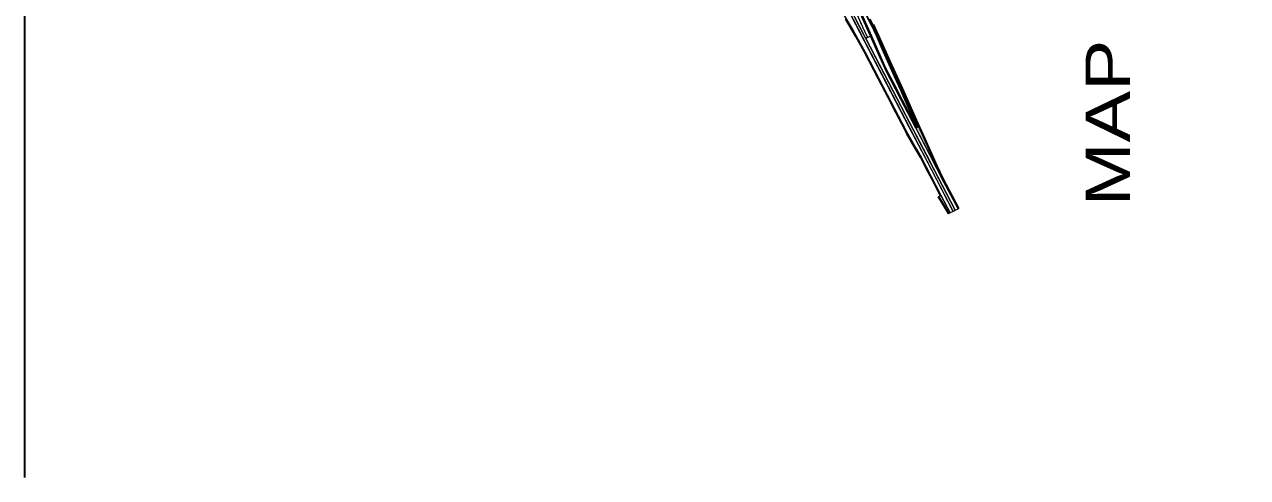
# Model space of a CAD drawing. Extents: x 2363427 to 2368559, y 6957299 to 6980140.
# Drawn here: x 2365247 to 2365851, y 6957299 to 6957523 of the extents above; entities that cross this region are included whole.
import ezdxf

# ---------------------------------------------------------------- set-up
doc = ezdxf.new("R2010")
doc.units = 0
doc.header["$LTSCALE"] = 5.6
for name, color, linetype, lineweight in [('10', 7, 'Continuous', 13), ('11', 7, 'Continuous', 13), ('13', 7, 'Continuous', 13), ('62', 7, 'Continuous', 25)]:
    doc.layers.add(name, color=color, linetype=linetype, lineweight=lineweight)

msp = doc.modelspace()

# ---------------------------------------------------------------- hatches: boundary and pattern name
at = {"layer": '10'}
msp.add_hatch(color=256, dxfattribs=at).paths.add_polyline_path([(2365702.86, 6957429.007), (2365700.937, 6957432.322), (2365699.517, 6957434.742), (2365697.773, 6957437.395), (2365698.004, 6957437.539), (2365699.486, 6957435.283), (2365700.763, 6957433.131), (2365703.117, 6957429.136)])
at = {"layer": '11'}
for points in [[(2365688.21, 6957472.074), (2365686.852, 6957471.368), (2365693.828, 6957457.945), (2365700.468, 6957445.022)], [(2365698.581, 6957437.914), (2365698.518, 6957437.952), (2365698.684, 6957437.894), (2365699.179, 6957438.26), (2365703.735, 6957429.475), (2365703.098, 6957429.134), (2365701.121, 6957432.553), (2365700.131, 6957434.237), (2365699.217, 6957435.619), (2365698.455, 6957436.878), (2365698.062, 6957437.539)]]:
    msp.add_hatch(color=256, dxfattribs=at).paths.add_polyline_path(points)

# ---------------------------------------------------------------- linework, layer by layer
at = {"layer": '10'}
for points in [[(2365613.714, 6957603.863), (2365613.047, 6957605.702), (2365612.352, 6957607.617), (2365611.157, 6957611.046), (2365618.042, 6957597.876), (2365623.831, 6957586.726), (2365705.198, 6957430.172), (2365703.735, 6957429.475), (2365699.179, 6957438.26), (2365689.241, 6957457.363), (2365682.53, 6957469.105), (2365661.998, 6957508.583), (2365656.036, 6957519.486), (2365650.672, 6957528.41), (2365651.571, 6957529.071), (2365652.36, 6957529.498)], [(2365705.199, 6957430.172), (2365694.44, 6957450.925), (2365683.512, 6957471.814), (2365668.035, 6957501.638), (2365652.671, 6957531.173), (2365641.176, 6957553.292), (2365631.851, 6957571.262), (2365623.866, 6957586.476), (2365625.116, 6957586.44), (2365631.129, 6957575.418), (2365633.902, 6957570.55), (2365643.536, 6957551.507), (2365656.466, 6957526.288), (2365669.134, 6957501.889), (2365706.205, 6957430.766)], [(2365686.845, 6957471.365), (2365679.457, 6957485.601), (2365671.697, 6957500.567), (2365669.769, 6957504.901), (2365663.727, 6957518.29), (2365657.952, 6957531.153), (2365655.792, 6957535.951), (2365651.817, 6957544.745), (2365649.417, 6957549.724), (2365646.294, 6957555.814), (2365641.88, 6957564.508), (2365642.254, 6957564.707), (2365644.694, 6957559.925), (2365646.626, 6957556.153), (2365650.419, 6957548.655), (2365652.099, 6957545.117), (2365655.362, 6957537.985), (2365659.059, 6957529.768), (2365664.821, 6957516.929), (2365668.38, 6957509.059), (2365672.035, 6957500.92), (2365675.744, 6957493.699), (2365680.1, 6957485.325), (2365687.223, 6957471.616)], [(2365662.071, 6957515.717), (2365681.876, 6957477.557), (2365691.975, 6957458.176), (2365695.466, 6957451.505), (2365706.208, 6957430.8), (2365707.637, 6957431.561), (2365700.468, 6957445.022), (2365693.828, 6957457.945), (2365672.395, 6957499.166), (2365671.67, 6957500.642), (2365668.897, 6957506.738), (2365664.401, 6957516.783)], [(2365702.86, 6957429.007), (2365700.937, 6957432.322), (2365699.517, 6957434.742), (2365697.773, 6957437.395), (2365698.004, 6957437.539), (2365699.486, 6957435.283), (2365700.763, 6957433.131), (2365703.117, 6957429.136)]]:
    msp.add_lwpolyline(points, close=True, dxfattribs=at)
for points in [[(2365651.464, 6957527.093), (2365655.913, 6957519.65), (2365661.838, 6957508.886), (2365670.86, 6957491.513), (2365678.121, 6957477.565), (2365682.201, 6957469.701), (2365684.358, 6957465.876), (2365687.166, 6957460.983), (2365689.402, 6957457.101), (2365699.133, 6957438.277), (2365698.733, 6957437.945), (2365694.945, 6957445.446), (2365692.797, 6957449.534), (2365689.02, 6957456.859), (2365686.455, 6957461.356), (2365682.228, 6957468.755), (2365679.884, 6957473.27), (2365676.881, 6957479.023), (2365673.056, 6957486.345), (2365668.134, 6957495.816), (2365661.28, 6957508.999), (2365657.195, 6957516.44), (2365655.594, 6957519.347), (2365652.091, 6957525.171)], [(2365659.544, 6957523.56), (2365661.632, 6957518.992), (2365662.938, 6957516.116), (2365662.071, 6957515.718), (2365661.135, 6957517.415), (2365659.119, 6957521.274), (2365656.818, 6957525.719)], [(2365662.642, 6957526.978), (2365665.442, 6957521.325), (2365667.763, 6957516.31), (2365670.889, 6957509.319), (2365674.028, 6957502.262), (2365680.158, 6957488.531), (2365687.63, 6957471.8), (2365687.487, 6957471.722), (2365685.852, 6957475.394), (2365684.057, 6957479.385), (2365682.004, 6957483.96), (2365680.569, 6957487.216), (2365679.313, 6957489.996), (2365676.323, 6957496.692), (2365670.214, 6957510.402), (2365667.315, 6957516.907), (2365666.016, 6957519.704), (2365664.902, 6957522.056), (2365662.16, 6957527.558)], [(2365665.865, 6957522.709), (2365669.392, 6957515.13), (2365674.171, 6957504.417), (2365680.121, 6957491.084), (2365685.754, 6957478.406), (2365688.561, 6957472.206), (2365690.508, 6957467.828), (2365697.326, 6957452.781), (2365700.221, 6957446.446), (2365708.03, 6957431.78), (2365707.64, 6957431.584), (2365700.559, 6957444.854), (2365698.852, 6957448.6), (2365698.027, 6957450.386), (2365694.729, 6957457.688), (2365688.208, 6957472.091), (2365683.934, 6957481.614), (2365678.248, 6957494.36), (2365674.764, 6957502.191), (2365668.834, 6957515.486), (2365665.853, 6957521.919), (2365664.293, 6957525.145)]]:
    msp.add_lwpolyline(points, dxfattribs=at)
at = {"layer": '11'}
msp.add_lwpolyline([(2365663.105, 6957526.108), (2365665.397, 6957521.459), (2365669.111, 6957513.311), (2365675.506, 6957498.989), (2365680.455, 6957487.955), (2365687.611, 6957471.836), (2365687.651, 6957471.783), (2365688.21, 6957472.074), (2365683.385, 6957482.896), (2365679.851, 6957490.82), (2365676.839, 6957497.516), (2365673.395, 6957505.268), (2365670.911, 6957510.807), (2365667.198, 6957519.079), (2365664.327, 6957525.067)], dxfattribs=at)
for points in [[(2365688.21, 6957472.074), (2365686.852, 6957471.368), (2365693.828, 6957457.945), (2365700.468, 6957445.022)], [(2365698.581, 6957437.914), (2365698.518, 6957437.952), (2365698.684, 6957437.894), (2365699.179, 6957438.26), (2365703.735, 6957429.475), (2365703.098, 6957429.134), (2365701.121, 6957432.553), (2365700.131, 6957434.237), (2365699.217, 6957435.619), (2365698.455, 6957436.878), (2365698.062, 6957437.539)]]:
    msp.add_lwpolyline(points, close=True, dxfattribs=at)
at = {"layer": '13'}
msp.add_lwpolyline([(2365656.042, 6957531.41), (2365660.508, 6957521.489), (2365662.936, 6957516.177), (2365664.401, 6957516.73), (2365660.435, 6957525.506)], dxfattribs=at)
at = {"layer": '62', "lineweight": 35}
msp.add_lwpolyline([(2366226.481, 6957951.933), (2365246.638, 6957951.933), (2365246.638, 6957298.789)], dxfattribs=at)

# ---------------------------------------------------------------- texts
at = {"layer": '62', "width": 1.3}
msp.add_text('MAP KEY', height=21.87, rotation=90, dxfattribs=at).set_placement((2365792.48, 6957432.699))

doc.saveas('drawing.dxf')
